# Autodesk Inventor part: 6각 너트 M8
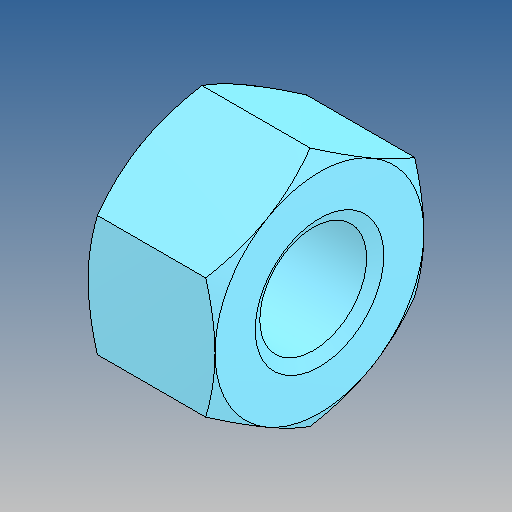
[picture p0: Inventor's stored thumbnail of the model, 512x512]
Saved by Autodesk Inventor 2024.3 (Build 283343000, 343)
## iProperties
Created: 2025-06
Part Number: 6각 너트 M8
Material: 강철, 연강
Description: 6각 너트 및 6각 가는 너트
Document SubType Name: Modeling
Designer: user
Density: 7.85 g/cm^3
Appearance: 기본값
Author: jhkim
Sending System: Autodesk Inventor 2026
Preprocessor: ST-DEVELOPER v20.1
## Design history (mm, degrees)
node "6각 너트 M81"
node "솔리드1"
body "Solid1"
